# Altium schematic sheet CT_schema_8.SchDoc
size 147 x 119 mm
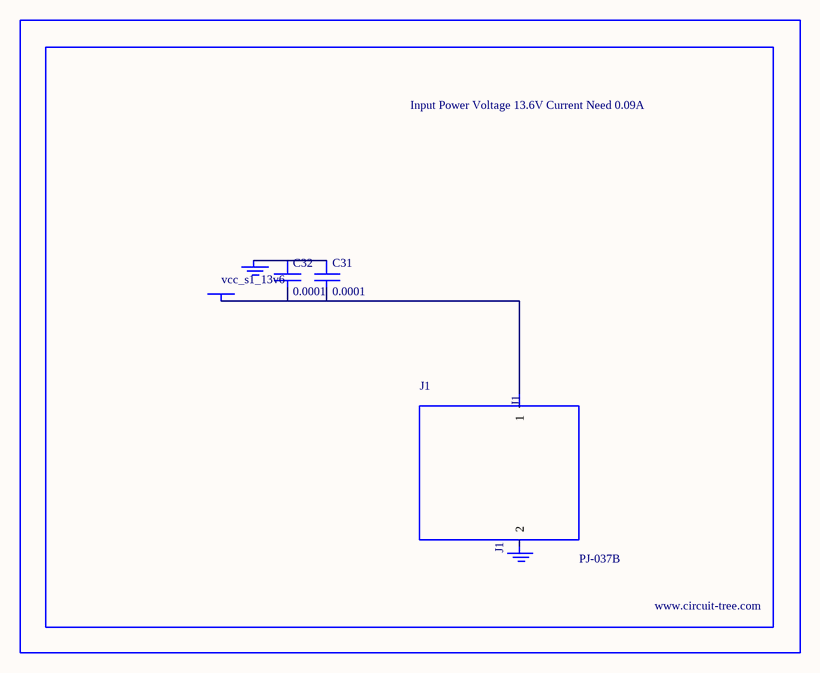
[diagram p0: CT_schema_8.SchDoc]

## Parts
BORDER7  (no value)
C31  0.0001  [EXV-9H]
C32  0.0001  [EXV-9H]
GND_INSTANCE_7_0  (no value)
GND_INSTANCE_7_1  (no value)
J1  PJ-037B  [PJ-037B_PACKAGE]
POWER_INSTANCE_7_0  vcc_s1_13v6

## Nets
NetC31_1: C31.1 C32.1 GND_INSTANCE_7_0.0(GND)
NetC31_2: C31.2 C32.2 J1.1 POWER_INSTANCE_7_0.0(PWR)

Not connected (* = marked no-connect by the designer): GND_INSTANCE_7_1 0(GND); J1 2

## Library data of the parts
BORDER7 = BORDER_PAGE7
C31 C32 = EDK107M035A9HAA
GND_INSTANCE_7_0 GND_INSTANCE_7_1 = GND
POWER_INSTANCE_7_0 = PWR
